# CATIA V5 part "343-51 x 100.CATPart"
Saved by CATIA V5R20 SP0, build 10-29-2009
Part number: 343-51 x 100
Definition: NONE
Nomenclature: 343-51 x 100
Source: Unknown
Description: 343-51 x 100
Bounding box of the stored display mesh (mm): x 0 to 100, y -35 to 35, z -35 to 35
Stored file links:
  C:\Users\Utente\Desktop\IO LAVORO\3D X SITO CF\X SITO\343-348\343-51 x 100.CATPart
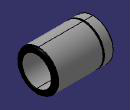
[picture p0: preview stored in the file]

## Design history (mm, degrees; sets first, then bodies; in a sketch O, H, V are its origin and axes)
Body1 "343-51 x 100" (main body)
  Solid1: solid without history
